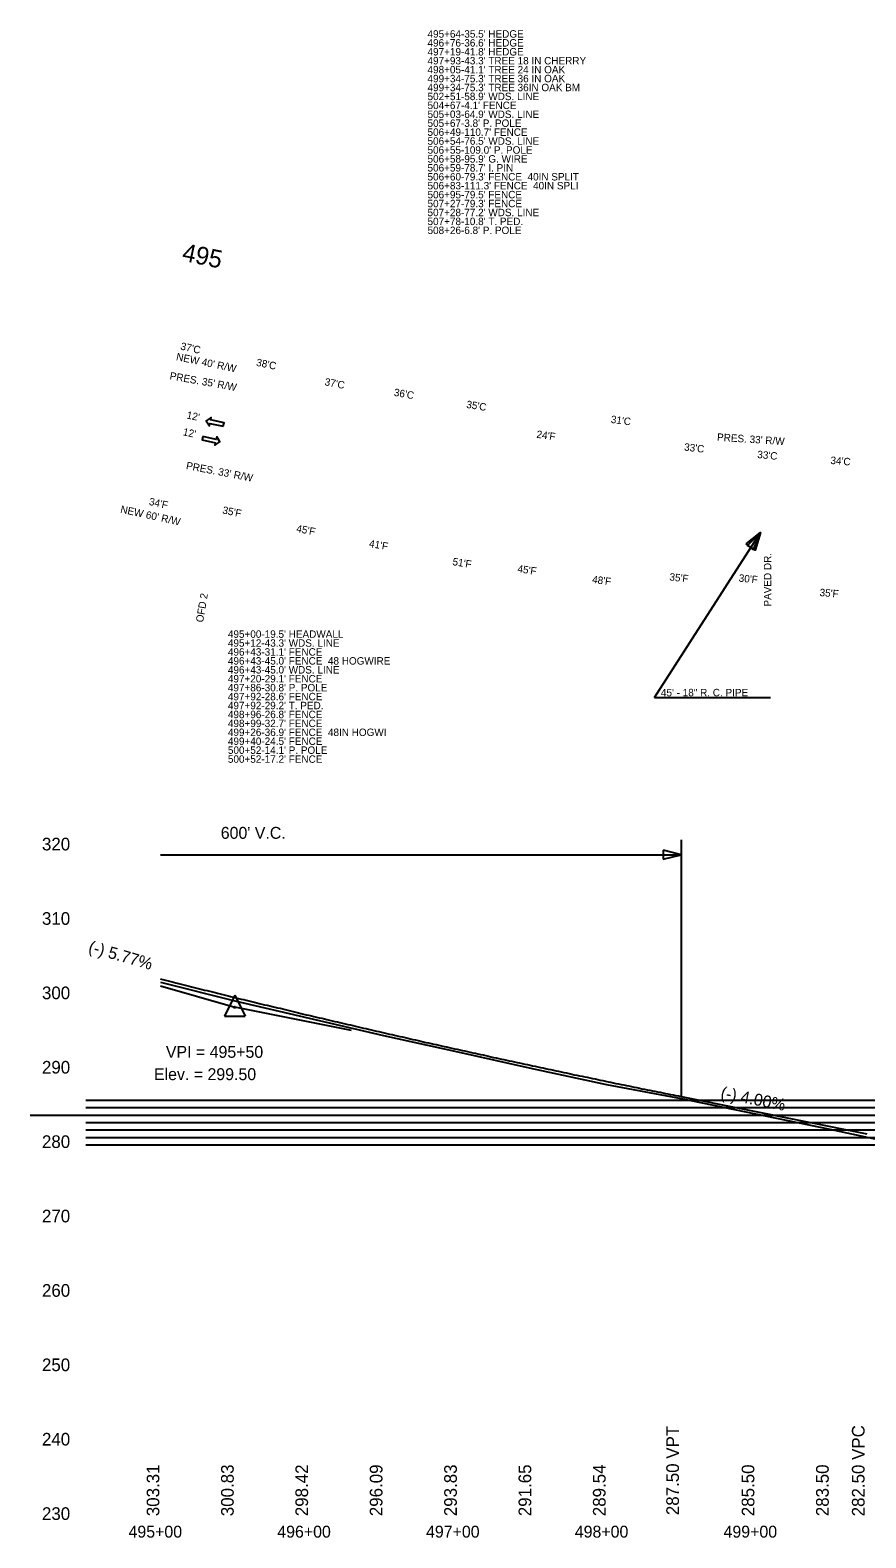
# Model space of a CAD drawing. Extents: x 49241 to 62599, y 49216 to 56011.
# Drawn here: x 50156 to 50718, y 50366 to 51380 of the extents above; entities that cross this region are included whole.
import ezdxf

# ---------------------------------------------------------------- set-up
doc = ezdxf.new("R2010")
doc.units = 0
for name, color, linetype in [('Level 1', 7, 'Continuous'), ('Level 13', 7, 'Continuous'), ('Level 14', 7, 'Continuous'), ('Level 18', 7, 'Continuous'), ('Level 2', 7, 'Continuous'), ('Level 21', 7, 'Continuous'), ('Level 23', 7, 'Continuous'), ('Level 24', 7, 'Continuous'), ('Level 40', 7, 'Continuous'), ('Level 41', 7, 'Continuous'), ('Level 42', 7, 'Continuous'), ('Level 43', 7, 'Continuous'), ('Level 45', 7, 'Continuous'), ('Level 6', 7, 'Continuous'), ('Level 8', 7, 'Continuous')]:
    doc.layers.add(name, color=color, linetype=linetype)

msp = doc.modelspace()

# ---------------------------------------------------------------- linework, layer by layer
at = {"layer": 'Level 1'}
for p, q in [((50193.5, 50660.3), (51793.3, 50660.3)), ((50193.5, 50655.3), (51793.3, 50655.3)), ((50193.5, 50645.3), (51793.3, 50645.3)), ((50193.5, 50640.3), (51793.3, 50640.3)), ((50193.5, 50635.3), (51793.3, 50635.3)), ((50193.5, 50630.3), (51793.3, 50630.3))]:
    msp.add_line(p, q, dxfattribs=at)
at = {"layer": 'Level 14'}
for points in [[(50285.8, 51113.3), (50286.3, 51115.7), (50277.3, 51117.6), (50277.7, 51119.2), (50274.3, 51117), (50276.5, 51113.6), (50276.8, 51115.2)], [(50272.1, 51106.4), (50271.6, 51104.1), (50280.5, 51102.2), (50280.2, 51100.6), (50283.5, 51102.8), (50281.4, 51106.1), (50281, 51104.5)]]:
    msp.add_lwpolyline(points, close=True, dxfattribs=at)
at = {"layer": 'Level 2'}
msp.add_line((50156, 50650.3), (51831.8, 50650.3), dxfattribs=at)
at = {"layer": 'Level 24'}
for points in [[(50637.3, 51034.2), (50647, 51041.8), (50642, 51030.5)], [(50638.2, 51033.1), (50647, 51041.8), (50643.3, 51030)]]:
    msp.add_lwpolyline(points, close=True, dxfattribs=at)
at = {"layer": 'Level 40'}
msp.add_lwpolyline([(50243.5, 50739.6), (50293.5, 50727), (50343.5, 50715.5), (50393.5, 50703.8), (50443.5, 50692.8), (50493.5, 50681.7), (50543.5, 50670.9), (50593.5, 50661.4), (50643.5, 50651.2), (50693.5, 50640.9), (50743.5, 50630)], dxfattribs=at)
at = {"layer": 'Level 41'}
for p, q in [((50593.5, 50835.3), (50593.5, 50662.8)), ((50243.5, 50825.3), (50593.5, 50825.3)), ((50593.5, 50825.3), (50581.5, 50828.3)), ((50581.5, 50828.3), (50581.5, 50822.3)), ((50581.5, 50822.3), (50593.5, 50825.3)), ((50243.5, 50737.2), (50293.5, 50722.8)), ((50293.5, 50730.8), (50286.5, 50716.8)), ((50293.5, 50730.8), (50300.5, 50716.8)), ((50371.9, 50707.1), (50293.5, 50722.8)), ((50286.5, 50716.8), (50300.5, 50716.8))]:
    msp.add_line(p, q, dxfattribs=at)
msp.add_circle((50293.5, 50722.8), 0.5, dxfattribs=at)
at = {"layer": 'Level 45'}
msp.add_line((50593.5, 50662.8), (50718.5, 50637.8), dxfattribs=at)
msp.add_line((50593.5, 50662.8), (50718.5, 50637.8), dxfattribs=at)
msp.add_spline([(50243.5, 50741.8), (50250.5, 50740), (50257.5, 50738.3), (50264.5, 50736.5), (50271.5, 50734.8), (50278.5, 50733.1), (50285.5, 50731.4), (50292.5, 50729.6), (50299.5, 50727.9), (50306.5, 50726.2), (50313.5, 50724.5), (50320.5, 50722.9), (50327.5, 50721.2), (50334.5, 50719.5), (50341.5, 50717.8), (50348.5, 50716.2), (50355.5, 50714.5), (50362.5, 50712.9), (50369.5, 50711.3), (50376.5, 50709.6), (50383.5, 50708), (50390.5, 50706.4), (50397.5, 50704.8), (50404.5, 50703.2), (50411.5, 50701.6), (50418.5, 50700), (50425.5, 50698.4), (50432.5, 50696.9), (50439.5, 50695.3), (50446.5, 50693.8), (50453.5, 50692.2), (50460.5, 50690.7), (50467.5, 50689.1), (50474.5, 50687.6), (50481.5, 50686.1), (50488.5, 50684.6), (50495.5, 50683.1), (50502.5, 50681.6), (50509.5, 50680.1), (50516.5, 50678.6), (50523.5, 50677.1), (50530.5, 50675.7), (50537.5, 50674.2), (50544.5, 50672.7), (50551.5, 50671.3), (50558.5, 50669.9), (50565.5, 50668.4), (50572.5, 50667), (50579.5, 50665.6), (50586.5, 50664.2), (50593.5, 50662.8)], degree=3, dxfattribs=at)
msp.add_spline([(50243.5, 50741.8), (50250.5, 50740), (50257.5, 50738.3), (50264.5, 50736.5), (50271.5, 50734.8), (50278.5, 50733.1), (50285.5, 50731.4), (50292.5, 50729.6), (50299.5, 50727.9), (50306.5, 50726.2), (50313.5, 50724.5), (50320.5, 50722.9), (50327.5, 50721.2), (50334.5, 50719.5), (50341.5, 50717.8), (50348.5, 50716.2), (50355.5, 50714.5), (50362.5, 50712.9), (50369.5, 50711.3), (50376.5, 50709.6), (50383.5, 50708), (50390.5, 50706.4), (50397.5, 50704.8), (50404.5, 50703.2), (50411.5, 50701.6), (50418.5, 50700), (50425.5, 50698.4), (50432.5, 50696.9), (50439.5, 50695.3), (50446.5, 50693.8), (50453.5, 50692.2), (50460.5, 50690.7), (50467.5, 50689.1), (50474.5, 50687.6), (50481.5, 50686.1), (50488.5, 50684.6), (50495.5, 50683.1), (50502.5, 50681.6), (50509.5, 50680.1), (50516.5, 50678.6), (50523.5, 50677.1), (50530.5, 50675.7), (50537.5, 50674.2), (50544.5, 50672.7), (50551.5, 50671.3), (50558.5, 50669.9), (50565.5, 50668.4), (50572.5, 50667), (50579.5, 50665.6), (50586.5, 50664.2), (50593.5, 50662.8)], degree=3, dxfattribs=at)
at = {"layer": 'Level 6'}
for q in [(50647, 51041.8), (50653.7, 50931)]:
    msp.add_line((50575.7, 50931), q, dxfattribs=at)

# ---------------------------------------------------------------- texts
at = {"layer": 'Level 1'}
msp.add_text('OFD 2', height=5, rotation=80.4346, dxfattribs=at).set_placement((50272.2, 50981.2))
at = {"layer": 'Level 13'}
for s, rotation, p in [("NEW 40' R/W", 348.3231, (50253.8, 51157.8)), ("PRES. 35' R/W", 349.9231, (50249.5, 51144.9)), ("PRES. 33' R/W", 356.2588, (50617.6, 51103.6)), ("PRES. 33' R/W", 349.1282, (50260.5, 51084.6)), ("NEW 60' R/W", 347.6766, (50216.3, 51055.3))]:
    msp.add_text(s, height=5, rotation=rotation, dxfattribs=at).set_placement(p)
at = {"layer": 'Level 18'}
for s, rotation, p in [("37'C", 347.419, (50256.7, 51164.9)), ("38'C", 348.294, (50307.6, 51154)), ("37'C", 349.169, (50353.6, 51140.9)), ("36'C", 350.044, (50400.2, 51133.8)), ("35'C", 350.919, (50448.9, 51125.7)), ("31'C", 352.6689, (50546.1, 51115.6)), ("24'F", 351.794, (50496.1, 51105.6)), ("33'C", 353.5439, (50595.4, 51097)), ("33'C", 354.4189, (50644.6, 51092)), ("34'C", 355.294, (50693.8, 51088)), ("34'F", 347.419, (50235.5, 51060.5)), ("35'F", 348.294, (50284.9, 51054.7)), ("45'F", 349.169, (50334.6, 51042.3)), ("41'F", 350.044, (50383.5, 51032.2)), ("51'F", 350.919, (50439.6, 51020)), ("45'F", 351.794, (50483.3, 51015.2)), ("35'F", 353.544, (50585.5, 51009.7)), ("48'F", 352.669, (50533.5, 51008)), ("30'F", 354.4189, (50632.1, 51008.9)), ("35'F", 355.294, (50686.5, 50999.2))]:
    msp.add_text(s, height=5, rotation=rotation, dxfattribs=at).set_placement(p)
at = {"layer": 'Level 21'}
msp.add_text('495', height=12, rotation=348.3095, dxfattribs=at).set_placement((50257.5, 51224.7))
at = {"layer": 'Level 23'}
for p in [(50260.8, 51118.6), (50258.3, 51107.3)]:
    msp.add_text("12'", height=5, rotation=348.1022, dxfattribs=at).set_placement(p)
at = {"layer": 'Level 24'}
for s, p in [("495+64-35.5' HEDGE", (50423.1, 51374.5)), ("496+76-36.6' HEDGE", (50423.1, 51368.5)), ("497+19-41.8' HEDGE", (50423.1, 51362.5)), ("497+93-43.3' TREE 18 IN CHERRY", (50423.1, 51356.5)), ("498+05-41.1' TREE 24 IN OAK", (50423.1, 51350.5)), ("499+34-75.3' TREE 36 IN OAK", (50423.1, 51344.5)), ("499+34-75.3' TREE 36IN OAK BM", (50423.1, 51338.5)), ("502+51-58.9' WDS. LINE", (50423.1, 51332.5)), ("504+67-4.1' FENCE", (50423.1, 51326.5)), ("505+03-64.9' WDS. LINE", (50423.1, 51320.5)), ("505+67-3.8' P. POLE", (50423.1, 51314.5)), ("506+49-110.7' FENCE", (50423.1, 51308.5)), ("506+54-76.5' WDS. LINE", (50423.1, 51302.5)), ("506+55-109.0' P. POLE", (50423.1, 51296.5)), ("506+58-95.9' G. WIRE", (50423.1, 51290.5)), ("506+59-78.7' I. PIN", (50423.1, 51284.5)), ("506+60-79.3' FENCE  40IN SPLIT", (50423.1, 51278.5)), ("506+83-111.3' FENCE  40IN SPLI", (50423.1, 51272.5)), ("506+95-79.5' FENCE", (50423.1, 51266.5)), ("507+27-79.3' FENCE", (50423.1, 51260.5)), ("507+28-77.2' WDS. LINE", (50423.1, 51254.5)), ("507+78-10.8' T. PED.", (50423.1, 51248.5)), ("508+26-6.8' P. POLE", (50423.1, 51242.5)), ("495+00-19.5' HEADWALL", (50288.9, 50971.1)), ("495+12-43.3' WDS. LINE", (50288.9, 50965.1)), ("496+43-31.1' FENCE", (50288.9, 50959.1)), ("496+43-45.0' FENCE  48 HOGWIRE", (50288.9, 50953.1)), ("496+43-45.0' WDS. LINE", (50288.9, 50947.1)), ("497+20-29.1' FENCE", (50288.9, 50941.1)), ("497+86-30.8' P. POLE", (50288.9, 50935.1)), ("497+92-28.6' FENCE", (50288.9, 50929.1)), ("497+92-29.2' T. PED.", (50288.9, 50923.1)), ("498+96-26.8' FENCE", (50288.9, 50917.1)), ("498+99-32.7' FENCE", (50288.9, 50911.1)), ("499+26-36.9' FENCE  48IN HOGWI", (50288.9, 50905.1)), ("499+40-24.5' FENCE", (50288.9, 50899.1)), ("500+52-14.1' P. POLE", (50288.9, 50893.1)), ("500+52-17.2' FENCE", (50288.9, 50887.1))]:
    msp.add_text(s, height=5, dxfattribs=at).set_placement(p)
at = {"layer": 'Level 41'}
for s, p in [("600' V.C.", (50284.1, 50836)), ('VPI = 495+50', (50247.2, 50688.8)), ('Elev. = 299.50', (50239.2, 50673.8))]:
    msp.add_text(s, height=8, dxfattribs=at).set_placement(p)
for s, rotation, p in [('(-) 5.77%', 343.9051, (50194.6, 50760)), ('(-) 4.00%', 348.6901, (50619.7, 50661.7))]:
    msp.add_text(s, height=8, rotation=rotation, dxfattribs=at).set_placement(p)
at = {"layer": 'Level 42'}
for s, height, p in [('320', 8.5, (50163.9, 50828.2)), ('310', 8.5, (50163.9, 50778.2)), ('300', 8.5, (50163.9, 50728.2)), ('290', 8.5, (50163.9, 50678.2)), ('280', 8.5, (50163.9, 50628.2)), ('270', 8.5, (50163.9, 50578.2)), ('260', 8.5, (50163.9, 50528.2)), ('250', 8.5, (50163.9, 50478.2)), ('240', 8.5, (50163.9, 50428.2)), ('230', 8.5, (50163.9, 50378.2)), ('495+00', 8, (50222.1, 50366.3)), ('496+00', 8, (50322.1, 50366.3)), ('497+00', 8, (50422.1, 50366.3)), ('498+00', 8, (50522.1, 50366.3)), ('499+00', 8, (50622.1, 50366.3))]:
    msp.add_text(s, height=height, dxfattribs=at).set_placement(p)
at = {"layer": 'Level 43'}
for s, p in [('287.50 VPT', (50592.1, 50381.4)), ('282.50 VPC', (50716.9, 50380.6)), ('303.31', (50242.8, 50380.7)), ('300.83', (50292.8, 50380.7)), ('298.42', (50342.8, 50380.7)), ('296.09', (50392.8, 50380.7)), ('293.83', (50442.8, 50380.7)), ('291.65', (50492.8, 50380.7)), ('289.54', (50542.8, 50380.7)), ('285.50', (50642.8, 50380.7)), ('283.50', (50692.8, 50380.7))]:
    msp.add_text(s, height=8.5, rotation=90, dxfattribs=at).set_placement(p)
at = {"layer": 'Level 6'}
msp.add_text('45\' - 18" R. C. PIPE', height=5, dxfattribs=at).set_placement((50580, 50931.8))
at = {"layer": 'Level 8'}
msp.add_text('PAVED DR.', height=5, rotation=90, dxfattribs=at).set_placement((50654.2, 50992.1))

doc.saveas('drawing.dxf')
